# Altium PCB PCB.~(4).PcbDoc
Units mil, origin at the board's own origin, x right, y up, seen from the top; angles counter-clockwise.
Board outline 2362.2 x 1653.54 mil, 4 copper layers (Top Layer, GND, PWR, Bottom Layer), stack 61.634 mil thick; 57 components, 24 nets, 132 pads, 50 vias.
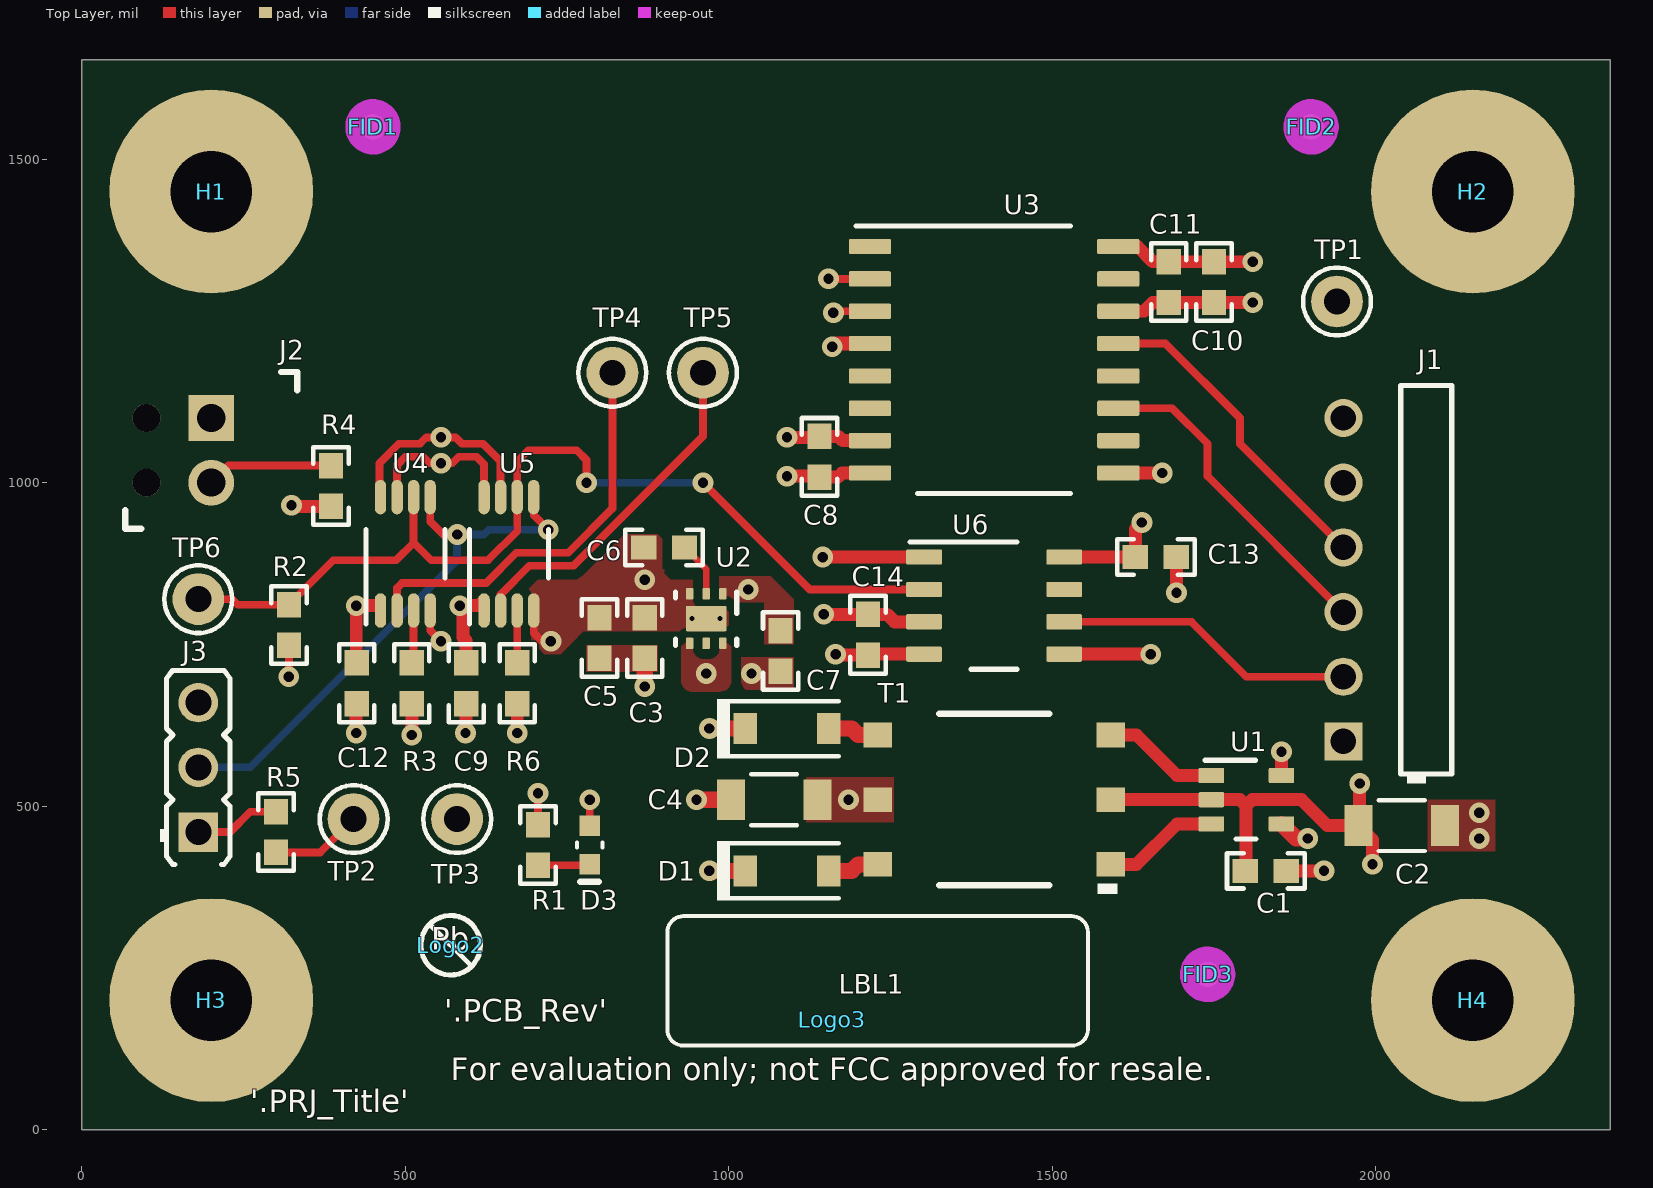
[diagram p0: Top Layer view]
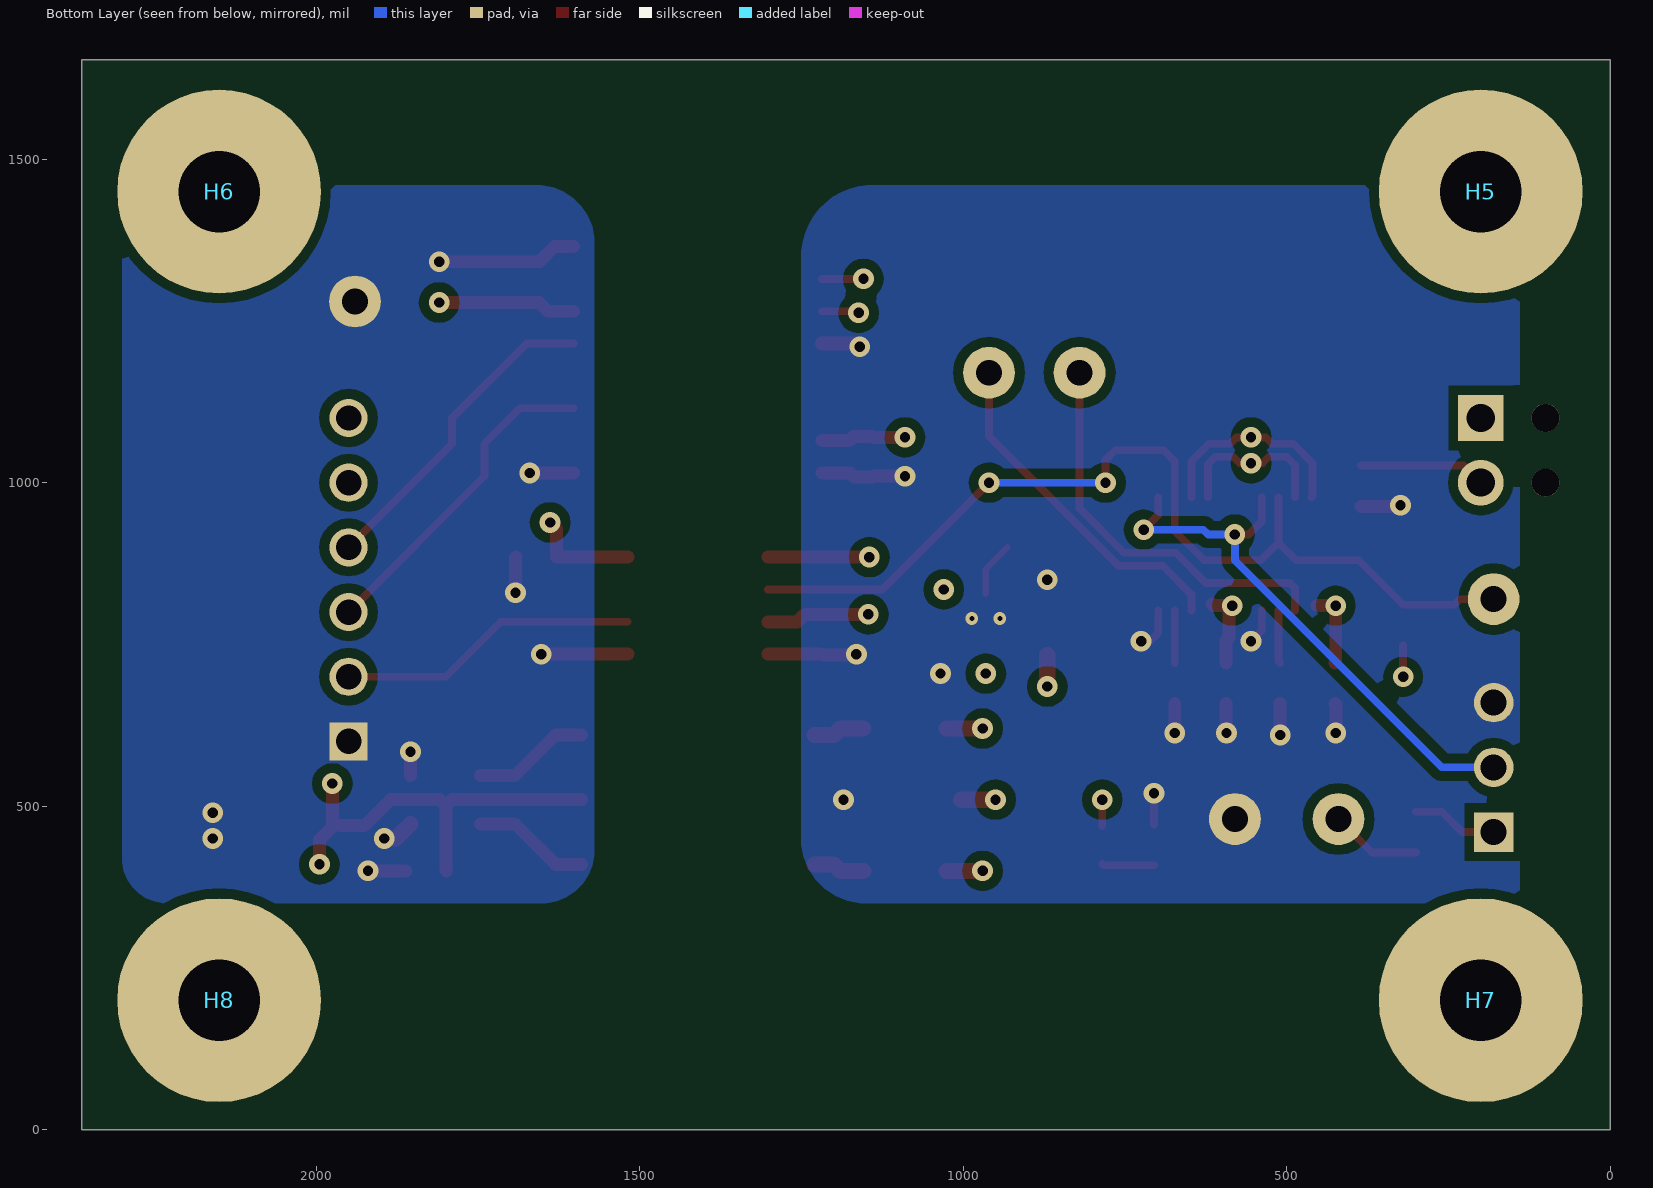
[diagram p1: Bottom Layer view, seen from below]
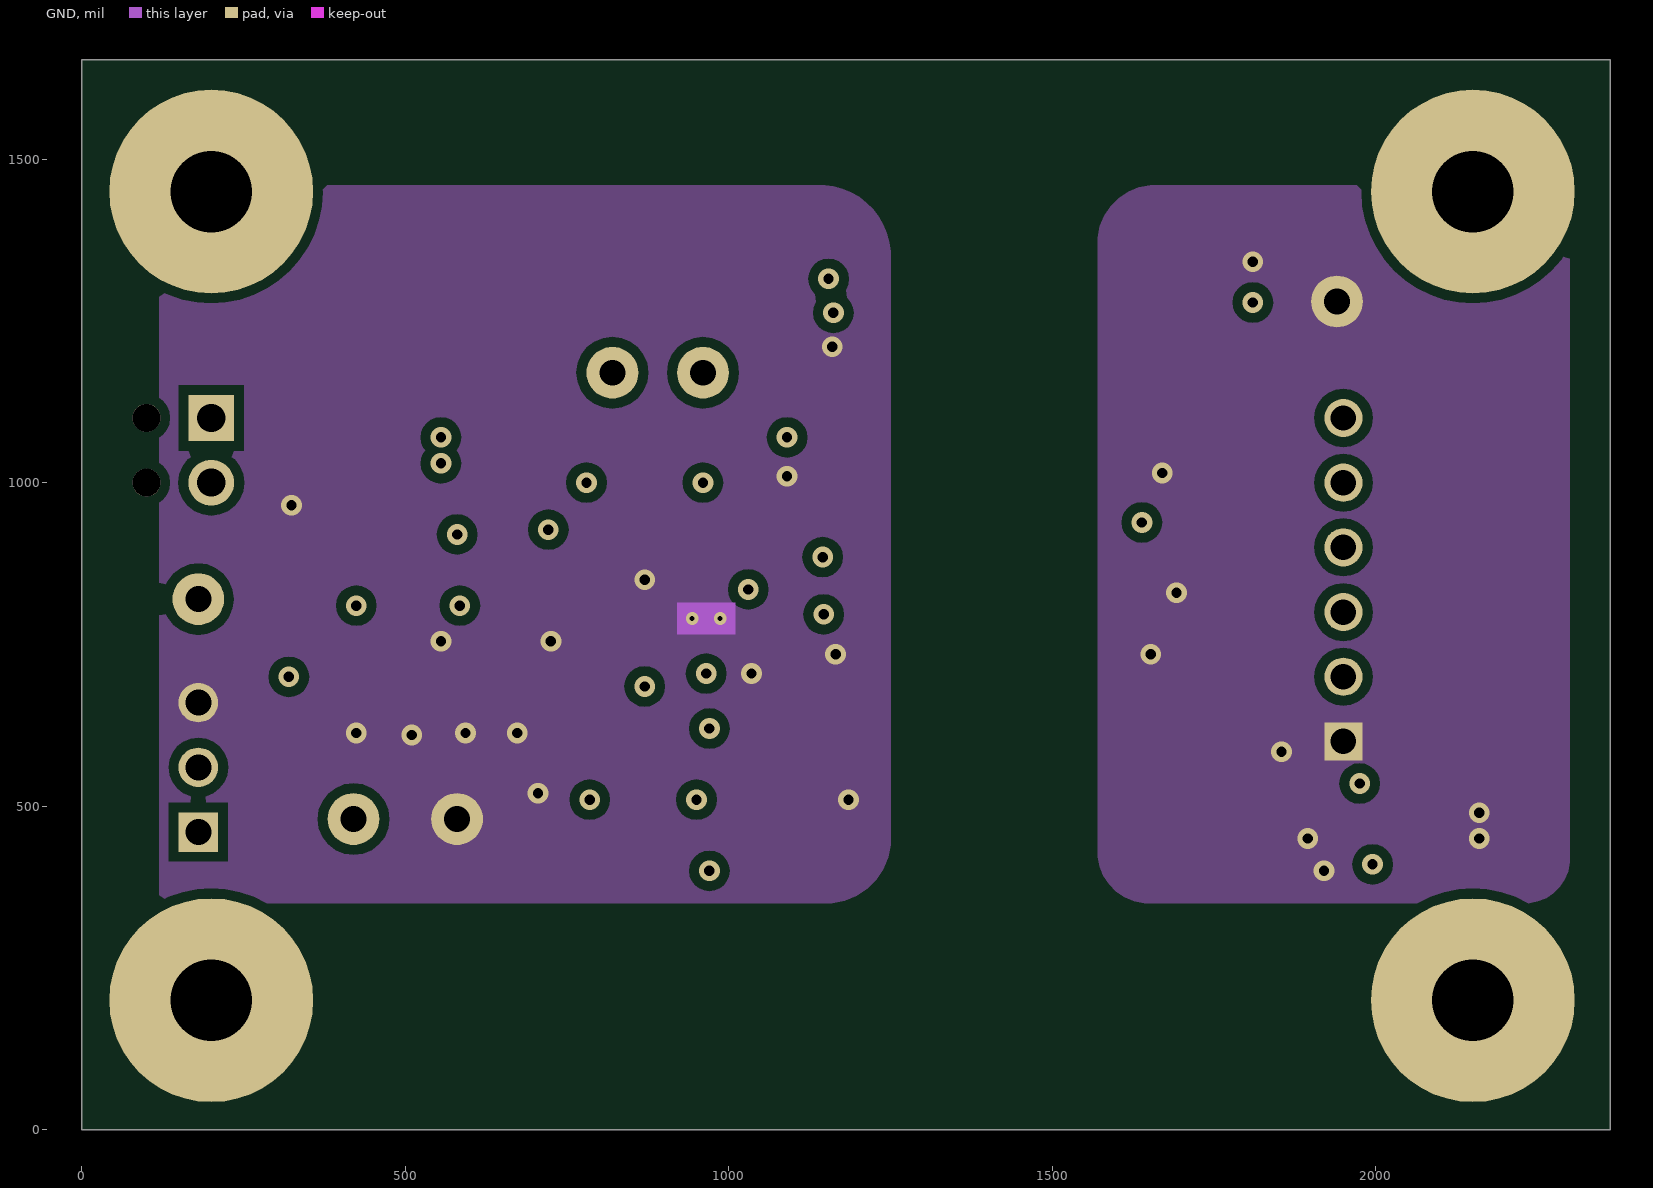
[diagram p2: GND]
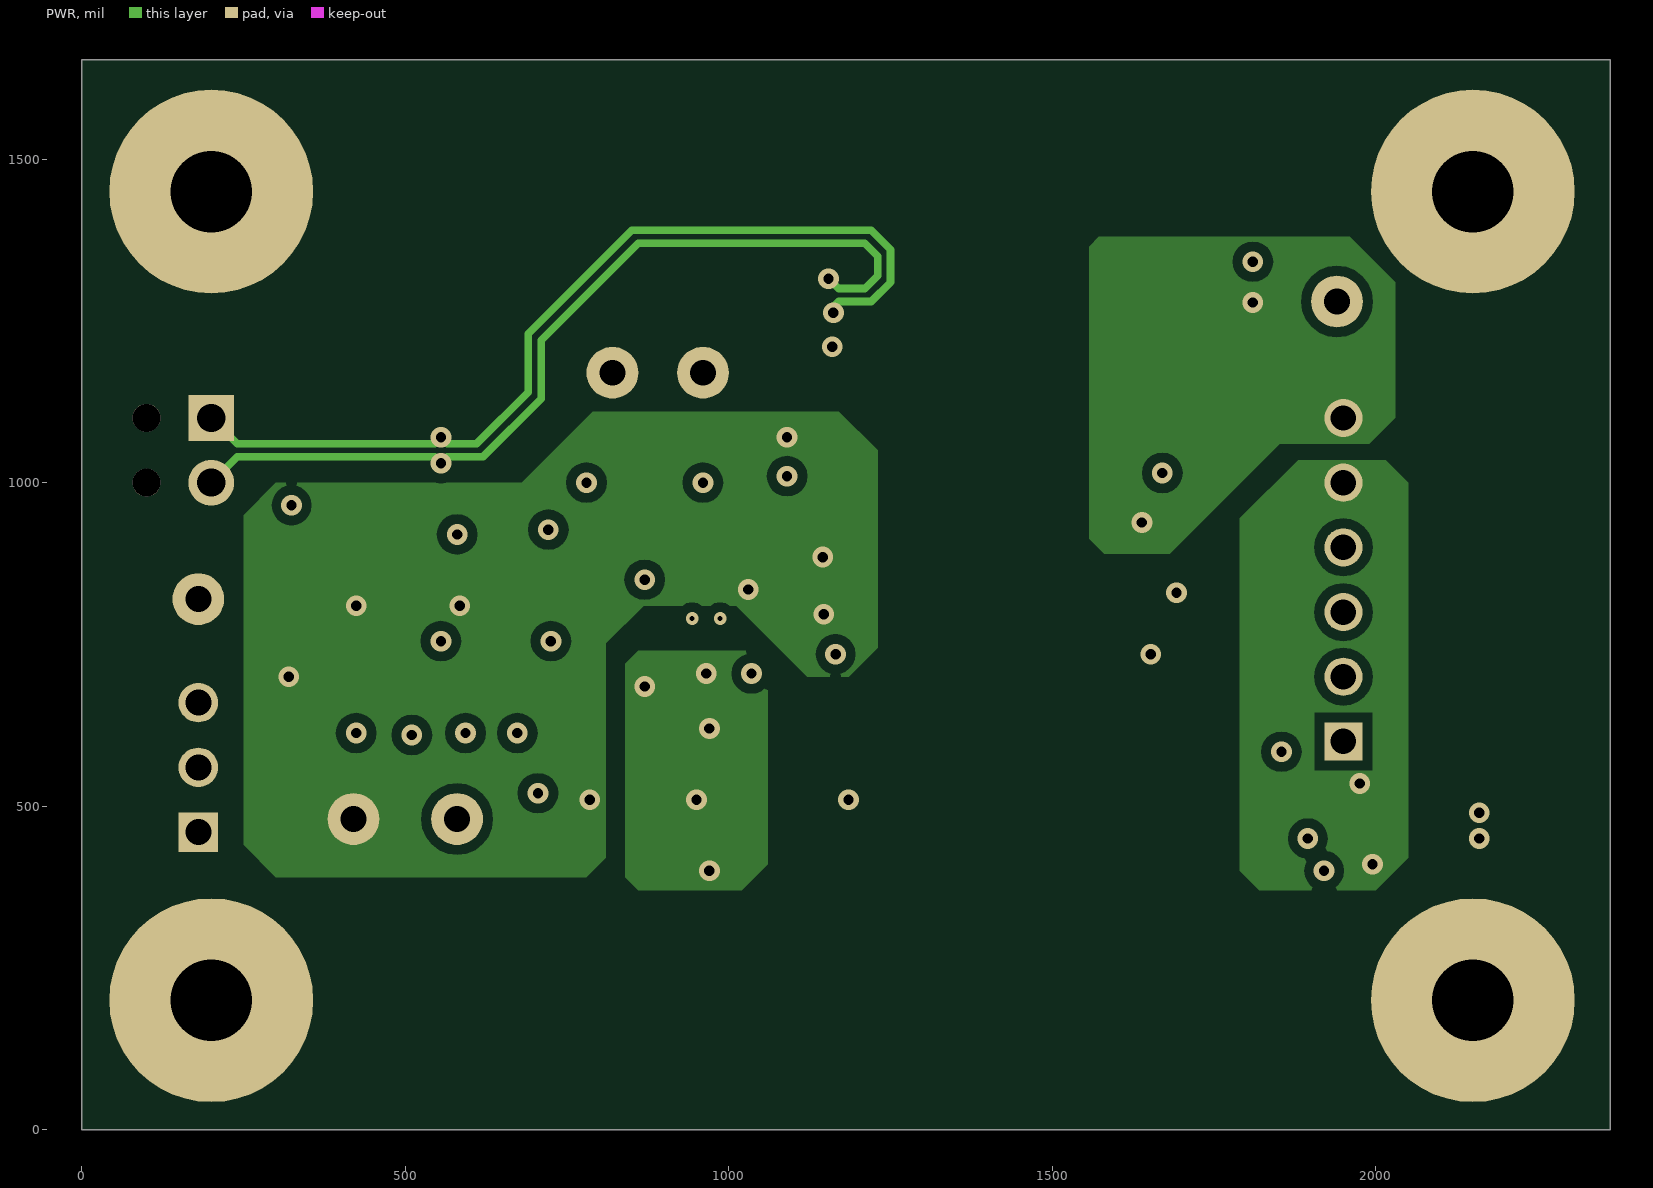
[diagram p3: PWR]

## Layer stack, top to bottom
Top Solder: solder mask 0.4, Solder Resist, Dk 3.5
Top Layer: signal copper 1.4
Dielectric1: core 18, FR-4 High Tg, Dk 4.2
GND: signal copper 1.417
Dielectric 2: prepreg 20, FR-4 High Tg, Dk 4.2
PWR: signal copper 1.417
Dielectric 3: core 18, FR-4 High Tg, Dk 4.2
Bottom Layer: signal copper 1.4
Bottom Solder: solder mask 0.4, Solder Resist, Dk 3.5

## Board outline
0,0 2362.2,0 2362.2,1653.54 0,1653.54

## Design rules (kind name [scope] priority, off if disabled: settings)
AcuteAngle [All] p1: minimum=4.50000000000000E+0001 checktracksonly=FALSE
AssemblyTestPointUsage [All] p1: valid=2
BoardOutlineClearance BoardOutlineClearance_MountingHoles [OnCopper and InComponentClass('Mounting Holes')] p1: gap=40 ignorepadtopadclearanceinfootprint=FALSE
BoardOutlineClearance BoardOutlineClearance_Poly [OnCopper and IsPoly] p2: gap=25 ignorepadtopadclearanceinfootprint=FALSE
BoardOutlineClearance [OnCopper and Not InComponentClass('Logo') and not InComponentClass('FiducialMark') and not InRegion(1000,500,4000,800) and not InPoly] p3: gap=75 ignorepadtopadclearanceinfootprint=FALSE
Clearance Clearance_Keepouts [((IsTrack Or IsArc) And Not InPoly) And IsFree and IsKeepOut vs ((IsTrack Or IsArc) And Not InPoly) And IsFree and IsKeepOut] p1: gap=0 ignorepadtopadclearanceinfootprint=FALSE
Clearance Clearance_Poly [InPolygon] p2: gap=7 ignorepadtopadclearanceinfootprint=TRUE except(15: Arc-Fill Arc-Poly Arc-Region Track-Fill Track-Poly Track-Region SMDPad-Fill SMDPad-Poly SMDPad-Region THPad-Fill THPad-Poly THPad-Region Via-Fill Via-Poly Via-Region Fill-Fill Fill-Poly Fill-Region Poly-Poly Poly-Region Region-Region)
Clearance Clearance_FiducialMark [IsKeepOut and InComponentClass('FiducialMark') vs IsPad and InComponentClass('FiducialMark')] p3: gap=0 ignorepadtopadclearanceinfootprint=FALSE
Clearance [All] p4: gap=7.85 ignorepadtopadclearanceinfootprint=TRUE
ComponentClearance ComponentClearance_MountingHoles_FiducialMarks [InComponentClass('Mounting Holes') vs InComponentClass('FiducialMark')] p1: gap=10 collisioncheckmode=3 verticalgap=10 showdistances=FALSE
ComponentClearance ComponentClearance_Shunt [InComponentClass('Header') vs InComponentClass('Shunt')] p2: gap=0 collisioncheckmode=3 verticalgap=0 showdistances=FALSE
ComponentClearance ComponentClearance_Logo [InComponentClass('Logo')] p3: gap=10 collisioncheckmode=3 verticalgap=10 showdistances=FALSE
ComponentClearance ComponentClearance_ScrewToNut [(HasFootprint('NY PMS 440 0025 PH')) vs (HasFootprint('Keystone_1902C'))] p4: gap=5 collisioncheckmode=3 verticalgap=10 showdistances=FALSE
ComponentClearance ComponentClearance_MountingHoles [InComponentClass('Mounting Holes')] p5: gap=10 collisioncheckmode=3 verticalgap=100000 showdistances=FALSE
ComponentClearance ComponentClearance_SmallPassives [HasFootprint('0201*') or HasFootprint('0402*') or HasFootprint('0508') or HasFootprint('0603*') or HasFootprint('0612') or HasFootprint('0805*') or HasFootprint('0815*') or HasFootprint('0830*') or HasFootprint('1206*') or HasFootprint('1210*') or HasFootprint('1808*') or HasFootprint('1812*') or HasFootprint('1825*') or HasFootprint('2010*') or HasFootprint('2220*') or HasFootprint('2225*') or HasFootprint('2512*') or HasFootprint('2728*') or HasFootprint('3518*') vs HasFootprint('0201*') or HasFootprint('0402*') or HasFootprint('0508') or HasFootprint('0603*') or HasFootprint('0612') or HasFootprint('0805*') or HasFootprint('0815*') or HasFootprint('0830*') or HasFootprint('1206*') or HasFootprint('1210*') or HasFootprint('1808*') or HasFootprint('1812*') or HasFootprint('1825*') or HasFootprint('2010*') or HasFootprint('2220*') or HasFootprint('2225*') or HasFootprint('2512*') or HasFootprint('2728*') or HasFootprint('3518*')] p6: gap=14.96 collisioncheckmode=3 verticalgap=10 showdistances=FALSE
ComponentClearance ComponentClearance_THtoSMT [IsThruComponent vs IsSMTComponent] p7: gap=40 collisioncheckmode=3 verticalgap=30 showdistances=FALSE
ComponentClearance ComponentClearance_THtoTH [IsThruComponent vs IsThruComponent] p8: gap=30 collisioncheckmode=3 verticalgap=30 showdistances=FALSE
ComponentClearance [All] p9: gap=20 collisioncheckmode=3 verticalgap=10 showdistances=FALSE
DiffPairsRouting [All] p1: maxlimit=100 minlimit=10 mostfreqgap=10 toplayer_minwidth=15 toplayer_maxwidth=15 toplayer_prefwidth=15 midlayer1_minwidth=15 midlayer1_maxwidth=15 midlayer1_prefwidth=15 midlayer2_minwidth=15 midlayer2_maxwidth=15 midlayer2_prefwidth=15 bottomlayer_minwidth=15 bottomlayer_maxwidth=15 bottomlayer_prefwidth=15 maxuncoupledlength=1000
FabricationTestPointUsage TestPointUsage [All] p1: valid=2 allowmultiple=FALSE
FabricationTestpoint Testpoint [All] p1: side=3 testpointundercomponent=TRUE minsize=40 maxsize=100 preferedsize=60 minholesize=0 maxholesize=40 preferedholesize=32 testpointgrid=1 allowsidetop=TRUE allowsidebottom=TRUE usegrid=TRUE gridtolerance=0.01
FanoutControl Fanout_LCC [IsLCC] p1: bgadir=Out bgaviamode=Centered fanoutstyle=Auto fanoutdirection=Alternating viagrid=1 // Fanout_LCC (Default Rule)
FanoutControl Fanout_BGA [IsBGA] p2: bgadir=Out bgaviamode=Centered fanoutstyle=Auto fanoutdirection=Alternating viagrid=1 // Fanout_BGA (Default Rule)
FanoutControl Fanout_Default [All] p4: bgadir=Out bgaviamode=Centered fanoutstyle=Auto fanoutdirection=Alternating viagrid=1 // Fanout_Default (Default Rule)
FanoutControl Fanout_Small [(CompPinCount < 5)] p5: bgadir=Out bgaviamode=Centered fanoutstyle=Auto fanoutdirection=OutThenIn viagrid=1 // Fanout_Small (Default Rule)
HoleSize [All] p1: absolutevalues=TRUE maxlimit=251 minlimit=7.87 maxpercent=80.000 minpercent=20.000
MinimumAnnularRing MinimumAnnularRing_ThermalPadVias [IsVia and InAnyComponent] p1: minimumring=5.91
MinimumAnnularRing [All] p2: minimumring=8
MinimumSolderMaskSliver MinimumSolderMaskSliver_Logo [InComponentClass('Logo') vs InComponentClass('Logo')] p1: minsoldermaskwidth=0.7
MinimumSolderMaskSliver [All] p2: minsoldermaskwidth=3.94
PlaneClearance [All] p1: clearance=5
PlaneConnect [All] p1: planeconnectstyle=Direct reliefexpansion=10 reliefentries=4 reliefconductorwidth=10 reliefairgap=10
PolygonConnect [All] p1: connectstyle=Direct reliefconductorwidth=10 reliefentries=4 polygonreliefangle="90 Angle" airgapwidth=10
RoutingVias ThermalPadVias [IsVia and InAnyComponent] p1: holewidth=7.87 width=19.68 viastyle="Through Hole" minholewidth=7.87 minwidth=19.68 maxholewidth=12.99 maxwidth=23.62
RoutingVias [All] p2: holewidth=16 width=34 viastyle="Through Hole" minholewidth=7.87 minwidth=26 maxholewidth=40 maxwidth=65
SilkToBoardRegionClearance [Not ((IsComment or IsDesignator) And (Hide <> 'False')) and not InRegion(1000,500,4000,800)] p1:
SilkToSilkClearance SilkToSilkClearance_Pb-FreeLogo [(HasFootprint('Pb-Free_Overlay_Medium') OR HasFootprint('Pb-Free_Overlay_Small')) vs (HasFootprint('Pb-Free_Overlay_Medium') OR HasFootprint('Pb-Free_Overlay_Small'))] p1: silktosilkclearance=0
SilkToSilkClearance [All] p2: silktosilkclearance=4
SilkToSolderMaskClearance SilkToComponentPadClearance [(IsPad or IsFill or IsRegion) and InAnycomponent] p1: minsilkscreentomaskgap=5 clearancetoexposedcopper=TRUE
SilkToSolderMaskClearance "Silk to Solder Mask Opening" [All] p2: minsilkscreentomaskgap=4 clearancetoexposedcopper=FALSE
SolderMaskExpansion [All] p1: expansion=1.97
Width [All] p1: maxlimit=100 minlimit=6 preferedwidth=10 checkconnectedcopper=TRUE
14 further rules are at their usual default settings.

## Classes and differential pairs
component class Label: LBL1
component class AssemblyNote: ZZ1 ZZ2 ZZ3 ZZ4
component class FiducialMark: FID1 FID2 FID3
component class EVM_Hardware: FID1 FID2 FID3 H1 H2 H3 H4 H5 H6 H7 H8 LBL1 Logo2 Logo3 ZZ1 ZZ2 ZZ3 ZZ4
component class "Mounting Holes": H1 H2 H3 H4
component class EVM_Main: C1 C2 C3 C4 C5 C6 C7 C8 C9 C10 C11 C12 C13 C14 D1 D2 D3 J1 J2 J3 R1 R2 R3 R4 R5 R6 T1 TP1 TP2 TP3 TP4 TP5 TP6 U1 U2 U3 U4 U5 U6
component class Header: J1 J3

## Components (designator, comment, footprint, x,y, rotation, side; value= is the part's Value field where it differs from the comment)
C1 "GCM188R71C104KA37J" 0603 1830,400 r180 top value=0.1uF
C2 "GRM31CR71C106KAC7L" 1206_180 2040,470 r0 top value=10uF
C3 "GCM188R71C104KA37J" 0603 870,760 r90 top value=0.1uF
C4 "GRM31CR71C106KAC7L" 1206_180 1070,510 r0 top value=10uF
C5 "GCM188R71C105KA64D" 0603 800,760 r90 top value=1uF
C6 "GRM188R71C103KA01D" 0603 900,900 r180 top value=0.01uF
C7 "GCM188R71C105KA64D" 0603 1080,740 r270 top value=1uF
C8 "GCM188R71C104KA37J" 0603 1140,1040 r270 top value=0.1uF
C9 "GCM188R71C104KA37J" 0603 594,690 r270 top value=0.1uF
C10 "GRM188R71C105KA12D" 0603 1750,1310 r270 top value=1uF
C11 "GCM188R71C104KA37J" 0603 1680,1310 r270 top value=0.1uF
C12 "GCM188R71C104KA37J" 0603 425,690 r270 top value=0.1uF
C13 "GCM188R71C104KA37J" 0603 1660,885 r0 top value=0.1uF
C14 "GCM188R71C104KA37J" 0603 1215,765 r270 top value=0.1uF
D1 "MBR0520LT1G" SOD-123 1090,400 r0 top value=20V
D2 "MBR0520LT1G" SOD-123 1090,620 r0 top value=20V
D3 "LG L29K-G2J1-24-Z" "LG L29K_GREEN" 785,440 r270 top value=Green
FID1 "Fiducial" Fiducial10-20 450,1550 r0 top
FID2 "Fiducial" Fiducial10-20 1900,1550 r0 top
FID3 "Fiducial" Fiducial10-20 1740,240 r0 top
H1 "NY PMS 440 0025 PH" "NY PMS 440 0025 PH" 200,1450 r0 top locked
H2 "NY PMS 440 0025 PH" "NY PMS 440 0025 PH" 2150,1450 r0 top locked
H3 "NY PMS 440 0025 PH" "NY PMS 440 0025 PH" 200,200 r0 top locked
H4 "NY PMS 440 0025 PH" "NY PMS 440 0025 PH" 2150,200 r0 top locked
H5 "1902C" Keystone_1902C 200,1450 r180 bottom locked
H6 "1902C" Keystone_1902C 2150,1450 r180 bottom locked
H7 "1902C" Keystone_1902C 200,200 r180 bottom locked
H8 "1902C" Keystone_1902C 2150,200 r180 bottom locked
J1 "90121-0766" Molex_90121-0766 1950,850 r90 top
J2 "1725656" CONN_1725656 200,1050 r270 top
J3 "0022284033" Molex_0022284033 180,560 r90 top
LBL1 "Size: 0.65\" x 0.20 \"" Label_650x200 1230,230 r0 top
Logo2 "Pb-Free Symbol" Pb-Free_Overlay_Small 570,285 r0 top
Logo3 "FCC disclaimer" FCC_disclaimer 1160,170 r0 top
R1 "CRCW06034K70JNEA" 0603 705,440 r270 top value=4.7k
R2 "CRCW060320K0FKEA" 0603 320,780 r270 top value=20.0k
R3 "CRCW060320K0FKEA" 0603 510,690 r90 top value=20.0k
R4 "CRCW06030000Z0EA" 0603 385,995 r90 top value=0
R5 "CRCW060320K0FKEA" 0603 300,460 r270 top value=20.0k
R6 "CRCW060320K0FKEA" 0603 673,690 r90 top value=20.0k
T1 "760390014" Wurth_760390013 1410,510 r180 top value=475uH
TP1 "5001" Keystone5001 1940,1280 r90 top
TP2 "5000" Keystone5000 420,480 r90 top
TP3 "5001" Keystone5001 580,480 r90 top
TP4 "5003" Keystone5003 820,1170 r90 top
TP5 "5003" Keystone5003 960,1170 r90 top
TP6 "5003" Keystone5003 180,820 r90 top
U1 "SN6501QDBVRQ1" DBV0005A_N 1800,510 r0 top
U2 "TPS71750QDRVRQ1" DRV0006A 965,790 r270 top
U3 "AMC1305M05QDWRQ1" DW0016B_HV 1410,1190 r0 top
U4 "INA301A2QDGKRQ1" DGK0008A_N 500,890 r90 top
U5 "INA301A2QDGKRQ1" DGK0008A_N 660,890 r90 top
U6 "ISO7710QDRQ1" D0008B_HV 1410,810 r0 top
ZZ1 "This Assembly Note is for PCB labels only" AssemblyNoteLabel 185,3938 r0 top
ZZ2 "This Assembly Note will show in the PcbDoc and associated outputs" AssemblyNote 185,3829.11 r0 top
ZZ3 "This Assembly Note will show in the PcbDoc and associated outputs" AssemblyNote 185,3740.56 r0 top
ZZ4 "This Assembly Note will show in the PcbDoc and associated outputs" AssemblyNote 185,3652 r0 top

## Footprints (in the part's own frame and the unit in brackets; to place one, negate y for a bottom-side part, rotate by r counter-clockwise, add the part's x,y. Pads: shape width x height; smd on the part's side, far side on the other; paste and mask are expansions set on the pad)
0603 [mm] "0603 from SM-752 data"
  rect 1x0.95 smd: 1(-0.8,0) 2(0.8,0)
  silkscreen extent -1.52,-0.69 1.52,0.69, body extent -0.87,-0.47 0.87,0.47, height 1
1206_180 [mm] "1206_180"
  rect 1.1x1.6 smd: 1(-1.7,0) 2(1.7,0)
  silkscreen extent -0.9,-1 0.9,1, body extent -1.75,-0.95 1.75,0.95, height 1.8
AssemblyNote [mil] "Assembly Note"
AssemblyNoteLabel [mil] "Assembly Note for PCB Labels"
CONN_1725656 [mm] "Phoenix Contact"
  rect 1.8x1.8 hole 1.1: 1(-1.27,0)
  round 1.8 hole 1.1: 2(1.27,0)
  round 1.1 hole 1.1 unplated paste+0 mask+0.152: MH1(-1.275,-2.54)
  round 1.1 hole 1.1 unplated mask+0.152: MH2(1.27,-2.54)
  silkscreen extent -3.08,-3.37 3.08,3.37, body extent -2.77,-3.1 2.77,3.1, height 8.52
D0008B_HV [mm] "SOIC, 8-Leads, Body 4.9x3.9mm, Pitch 1.27mm, HV / Isolation option"
  rrect17% 1.4x0.6 smd: 1(-2.75,1.905) 2(-2.75,0.635) 3(-2.75,-0.635) 4(-2.75,-1.905) 5(2.75,-1.905) 6(2.75,-0.635) 7(2.75,0.635) 8(2.75,1.905)
  silkscreen extent -3.3,-2.5 0.9,2.5, body extent -3,-2.45 3,2.45, height 1.63
DBV0005A_N [mm] "SOT23, 5-Leads, Body 2.9x1.6mm, Pitch 0.95mm, Lead Span 2.8mm, IPC Medium Density"
  rrect17% 1x0.6 smd: 1(-1.375,0.95) 2(-1.375,0) 3(-1.375,-0.95) 4(1.375,-0.95) 5(1.375,0.95)
  silkscreen extent -1.63,-1.55 0.38,1.55, body extent -1.42,-1.46 1.42,1.46, height 1.09
DGK0008A_N [mm] "TSOP, 8-Leads, Body 3x3mm, Pitch 0.65mm, IPC Medium Density"
  oval 1.35x0.45 smd: 1(-2.225,0.975) 2(-2.225,0.325) 3(-2.225,-0.325) 4(-2.225,-0.975) 5(2.225,-0.975) 6(2.225,-0.325) 7(2.225,0.325) 8(2.225,0.975)
  silkscreen extent -2.75,-1.55 0.95,1.55, body extent -2.45,-1.5 2.45,1.5, height 0.96
DRV0006A [mm] "SON, 6-Leads, Body 2x2mm, Pitch 0.65mm, Thermal Pad 1.6x1mm, TI Recommended"
  rrect33% 0.45x0.3 smd: 1(-0.975,0.65) 2(-0.975,0) 3(-0.975,-0.65) 4(0.975,-0.65) 5(0.975,0) 6(0.975,0.65)
  rrect14% 1x0.7 on Top Paste: 7(0,0.45) 7(0,-0.45)
  rrect10% 1x1.6 smd paste-0.5: 7(0,0)
  silkscreen extent -1.05,-1.2 1.05,1.2, body extent -1.05,-1.05 1.05,1.05, height 0.81
DW0016B_HV [mm] "High voltage version of DW0016B"
  rrect17% 1.65x0.6 smd: 1(-4.875,4.445) 2(-4.875,3.175) 3(-4.875,1.905) 4(-4.875,0.635) 5(-4.875,-0.635) 6(-4.875,-1.905) 7(-4.875,-3.175) 8(-4.875,-4.445) 9(4.875,-4.445) 10(4.875,-3.175) 11(4.875,-1.905) 12(4.875,-0.635) 13(4.875,0.635) 14(4.875,1.905) 15(4.875,3.175) 16(4.875,4.445)
  silkscreen extent -5.43,-5.25 3,5.25, body extent -5.14,-5.13 5.14,5.13, height 2.5
FCC_disclaimer [mil]
Fiducial10-20 [mm]
  round 1 smd mask+0.5: 1(0,0)
  Top Layer keep-out circle w1.178: c0,0 r0.5
Keystone5000 [mil] "For Keystone 500x miniature loop terminals"
  round 80 hole 40: 1(0,0)
  silkscreen extent -52,-52 52,52, body extent -49,-49 49,49, height 182
Keystone5001 [mil] "For Keystone 500x miniature loop terminals"
  round 80 hole 40: 1(0,0)
  silkscreen extent -52,-52 52,52, body extent -49,-49 49,49, height 182
Keystone5003 [mil] "For Keystone 500x miniature loop terminals"
  round 80 hole 40: 1(0,0)
  silkscreen extent -52,-52 52,52, body extent -49,-49 49,49, height 182
Keystone_1902C [mil] "Hex Standoff, 4-40 threaded, nylon"
  body extent -145,-126 146,126, height 501
Label_650x200 [mil] "Thermal Transfer Label"
  silkscreen extent -325,-100 325,100, body extent -325,-100 325,100, height 1
"LG L29K_GREEN" [mm] "OSRAM"
  rect 0.8x0.8 smd paste-0.4: 1(-0.75,0) 2(0.75,0)
  silkscreen extent -0.1,-0.5 1.45,0.5, body extent -0.9,-0.45 0.9,0.45, height 0.67
Molex_90121-0766 [mm] "Header, 2.54mm, 6x1, R/A, TH"
  rect 1.5x1.5 hole 1: 1(-6.35,0)
  round 1.5 hole 1: 2(-3.81,0) 3(-1.27,0) 4(1.27,0) 5(3.81,0) 6(6.35,0)
  silkscreen extent -8,-4.25 7.62,-2.25, body extent -7.62,-11 7.62,0.32, height 3.63
Molex_0022284033 [mm] "Header, 2.54mm, 3x1, TH"
  rect 1.55x1.55 hole 1.02: 1(-2.54,0)
  round 1.55 hole 1.02: 2(0,0) 3(2.54,0)
  silkscreen extent -3.81,-1.24 3.81,1.5, body extent -3.81,-1.24 3.81,1.24, height 8.4
"NY PMS 440 0025 PH" [mm] "4-40 nylon screw and mounting hole"
  round 8 hole 3.2: 1(0,0)
  body extent -3.3,-3.3 3.3,3.3, height 2.69
Pb-Free_Overlay_Small [mil]
  silkscreen extent -46,-46 46,46
SOD-123 [mm] "On Semi recommended land pattern"
  rect 0.915x1.22 smd: 1(-1.637,0) 2(1.637,0)
  silkscreen extent -2.74,-1.17 2.03,1.17, body extent -1.93,-0.9 1.93,0.9, height 1.35
Wurth_760390013 [mil] "Wurth"
  rect 44x38 smd: 1(-180,100) 2(-180,0) 3(-180,-100) 4(180,-100) 5(180,0) 6(180,100)
  silkscreen extent -190,-132 85,145, body extent -198,-135 198,130, height 166

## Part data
C1 C3 C8 C9 C11 C12 C13 C14: "CAP, CERM, 0.1 µF, 16 V,+/- 10%, X7R, AEC-Q200 Grade 1, 0603", Cap_Case=0603, Manufacturer=MuRata, Supplier Part Number 1=490-8015-1-ND, TempCo=X7R, Tolerance_%=10, Value1=Unknown, Value2=16V, ValueDisplayed=0.1µF
C2 C4: "CAP, CERM, 10 µF, 16 V,+/- 10%, X7R, 1206", Cap_Case=1206, Manufacturer=MuRata, Supplier Part Number 1=490-3911-1-ND, TempCo=X7R, Tolerance_%=10, Value1=Unknown, Value2=16V, ValueDisplayed=10µF
C5 C7: "CAP, CERM, 1 µF, 16 V,+/- 10%, X7R, AEC-Q200 Grade 1, 0603", Cap_Case=0603, Manufacturer=MuRata, Supplier Part Number 1=490-5241-6-ND, TempCo=X7R, Tolerance_%=10, Value1=Unknown, Value2=16V, ValueDisplayed=1µF
C6: "CAP, CERM, 0.01 µF, 16 V,+/- 10%, X7R, 0603", Cap_Case=0603, Manufacturer=MuRata, Supplier Part Number 1=490-1525-1-ND, TempCo=X7R, Tolerance_%=10, Value1=Unknown, Value2=16V, ValueDisplayed=0.01µF
C10: "CAP, CERM, 1 µF, 16 V,+/- 10%, X7R, 0603", Cap_Case=0603, Manufacturer=MuRata, Supplier Part Number 1=490-3900-1-ND, TempCo=X7R, Tolerance_%=10, Value1="0.011 ohm", Value2=16V, ValueDisplayed=1µF
D1 D2: "Diode, Schottky, 20 V, 0.5 A, SOD-123", Manufacturer="ON Semiconductor", Supplier Part Number 1=MBR0520LT1GOSCT-ND, Value1=0.5A, Value2=0.385V
D3: "LED, Green, SMD", Color=green, Manufacturer=OSRAM, Supplier Part Number 1=475-2709-1-ND, Value1=W, Value2=1.7V
FID1 FID2 FID3: "Fiducial mark.  There is nothing to buy or mount.", Manufacturer=N/A
H1 H2 H3 H4: "Machine Screw, Round, #4-40 x 1/4, Nylon, Philips panhead", DigiKeyPartNumber=H542-ND, Manufacturer="B&F Fastener Supply"
H5 H6 H7 H8: "Standoff, Hex, 0.5\"L #4-40 Nylon", Manufacturer=Keystone, Supplier Part Number 1=36-1902C-ND
J1: "Header, 2.54mm, 6x1, Gold, R/A, TH", Color=Black, Current_A=3, Manufacturer=Molex, Supplier Part Number 1=WM8112-ND, Voltage_V=350
J2: "Terminal Block, 100mil, 2x1, 6A, 63V, TH", Manufacturer="Phoenix Contact", Supplier Part Number 1=71C4107
J3: "Header, 2.54mm, 3x1, Tin, TH", Color=Black, Current_A=4, Manufacturer=Molex, Supplier Part Number 1=WM50016-03-ND, Voltage_V=250
LBL1: library part THT-14-423-10, "Thermal Transfer Printable Labels, 0.650\" W x 0.200\" H - 10,000 per roll", Manufacturer=Brady, Supplier Part Number 1=97C5133
Logo2: library part Pb-Free
Logo3: library part FCC_disclaimer, "FCC_disclaimer"
R1: "RES, 4.7 k, 5%, 0.1 W, 0603", Manufacturer=Vishay-Dale, Power_W=0.1, Supplier Part Number 1=541-4.7KGCT-ND, TempCo="200 ppm/C", Tolerance_%=5, Value1=5%, Value2=0.1W, Value_Code=4k70, ValueDisplayed=4.7k
R2 R3 R5 R6: "RES, 20.0 k, 1%, 0.1 W, 0603", Manufacturer=Vishay-Dale, Power_W=0.1, Supplier Part Number 1=541-20.0KHCT-ND, TempCo="100 ppm/C", Tolerance_%=1, Value1=1%, Value2=0.1W, Value_Code=20k0, ValueDisplayed=20.0k
R4: "RES, 0, 5%, 0.1 W, 0603", Manufacturer=Vishay-Dale, Power_W=0.1, Supplier Part Number 1=541-0.0GCT-ND, TempCo="200 ppm/C", Tolerance_%=5, Value1=5%, Value2=0.1W, Value_Code=0000, ValueDisplayed=0
T1: "Transformer, 475uH, SMT", Manufacturer="Wurth Elektronik", Supplier Part Number 1=732-4458-1-ND, ValueDisplayed=475µH
TP1 TP3: "Test Point, Miniature, Black, TH", Color=Black, Manufacturer=Keystone, Supplier Part Number 1=36-5001-ND
TP2: "Test Point, Miniature, Red, TH", Color=Red, Manufacturer=Keystone, Supplier Part Number 1=36-5000-ND
TP4 TP5 TP6: "Test Point, Miniature, Orange, TH", Color=Orange, Manufacturer=Keystone, Supplier Part Number 1=36-5003-ND
U1: "Automotive Low-Noise 350 mA, 410 kHz Transformer Driver, DBV0005A (SOT-23-5)", Alternate Manufacturer="Texas Instruments"
U2: library part CMP-0082419-1, "Low Noise, High-Bandwidth PSRR Low-Dropout 150mA Linear Regulator for Automotive Applications, DRV0006A (WSON-6)", Alternate Manufacturer="Texas Instruments", Operating Temperature Range="-40 to 125 C", Rating=Automotive
U3: library part CMP-0082424-1, "Automotive Reinforced Isolated Modulator With +/-50mV Input and CMOS Interface, DW0016B (SOIC-16)", Alternate Manufacturer="Texas Instruments", Alternate PartNumber=AMC1305M05QDWQ1, Operating Temperature Range="-40 to 125 C", Rating=Automotive
U4 U5: library part CMP-0082409-1, "AEC-Q100, 36V, Low-/High-side, Voltage Output CSA with Comparator, DGK0008A (VSSOP-8)", Alternate Manufacturer="Texas Instruments", Alternate PartNumber=INA301A2QDGKTQ1, Operating Temperature Range="-40 to 125 C", Rating=Automotive
U6: library part CMP-0082405-1, "Automotive, High Speed, Robust EMC Reinforced Single-Channel Digital Isolator, D0008B (SOIC-8)", Alternate Manufacturer="Texas Instruments", Alternate PartNumber=ISO7710QDQ1, Operating Temperature Range="-40 to 125 C", Rating=Automotive
ZZ1: library part AssemblyNoteLabel
ZZ2 ZZ3 ZZ4: library part AssemblyNote

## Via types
v1: diameter 32, hole 16, Top Layer to Bottom Layer, 48 vias
v2: diameter 19.68, hole 7.87, Top Layer to Bottom Layer, 2 vias

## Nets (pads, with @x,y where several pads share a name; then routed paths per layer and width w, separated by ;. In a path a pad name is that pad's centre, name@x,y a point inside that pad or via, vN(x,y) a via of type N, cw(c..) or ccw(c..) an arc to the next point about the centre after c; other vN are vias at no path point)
5V_ISO: C7.1 C8.1 C9.1 C12.1 C14.1 D3.1 R2.2 R5.2 TP2.1 U2.1 U3.7 U4.1 U5.1 U6.1 U6.3 | length 921
  Top Layer w12: R5.2 368.5,428.5 TP2.1 ; v1(320,700) R2.2 ; D3.1 v1(785,510)
  Top Layer w20: C12.1 424.13,722.36 v1(424.13,810) U4.1@452.76,810 ; C9.1 594,756 588.87,761.13 588.87,805.26 v1(584.13,810) 612.76,810 U5.1@615.47,812.72 ; v1(1090,1070) 1138.5,1070 C8.1 1169.77,1071.5 1176.27,1065 U3.7 ; v1(1145,885) U6.1 ; v1(1146.5,796.5) C14.1 1244.77,796.5 1256.27,785 U6.3
  other v1: 1030,835
ALERT: R2.1 TP6.1 U4.6 U5.6 U6.2 | length 1489.6
  Top Layer w12: TP6.1 232.5,820 241,811.5 R2.1 388.5,880 485.59,880 512.8,907.2 ; U4.6 512.8,907.2 ; v1(780,1000) 780,1035 765,1050 690,1050 672.8,1032.8 U5.6 672.8,925.19 627.61,880 540,880 512.8,907.2 ; v1(960,1000) 1125,835 U6.2
  Bottom Layer w12: v1(780,1000) v1(960,1000)
CLKIN: J1.4 U3.13 | length 502
  Top Layer w12: U3.13 1675,1215 1790,1100 1790,1060 J1.4
DOUT: J1.3 U3.11 | length 507.8
  Top Layer w12: U3.11 1685,1115 1740,1060 1740,1010 J1.3
GND: C1.1 C2.2 C10.1 C11.1 C13.2 J1.1 TP1.1 U1.4 U1.5 U3.9 U3.16 U6.5 | length 622.4
  Top Layer w20: U6.5 v1(1652,735) ; U3.9 v1(1670,1015) ; U3.16 1631.73,1365 1655.24,1341.5 v1(1810,1341.5) ; v1@1690,830 v1@1691.5,831.5 ; C13.2 1692,884.5 v1(1692,830) ; U1.5 v1(1854.13,584.13) ; C1.1 v1(1920,400)
  Top Layer w25: U1.4 1876.73,450 v1(1895,450)
  other v1: 2160,450 2160,490
ISOGND: C3.2 C4.2 C5.2 C6.2 C7.2 C8.2 C9.2 C12.2 C14.2 J3.3 R1.1 R3.1 R4.1 R6.1 T1.5 TP3.1 U2.3 U2.7@965,790 U3.4 U3.8 U4.4 U5.4 U6.4 | length 733.6
  Top Layer w12: U4.4 538.39,771.61 v1(555,755) ; U5.4 698.39,767.6 710.98,755 v1(725,755) ; R1.1 v1(705,520)
  Top Layer w20: v1@323.5,963.5 R4.1 ; v1(424,613) 424,657.5 C12.2 ; v1(510,610) R3.1 ; v1(593,613) 594,614 C9.2 ; v1(673,613) R6.1 ; v1(1090,1010) 1138.5,1010 C8.2 1168.5,1008.5 1175,1015 U3.8 ; v1(1165,735) 1166.5,733.5 C14.2 ; C14.2@1220,735 U6.4
  Top Layer w21.81: v1@1165,1215 U3.4
  other v1: 1185,510 1035,705 870,850 324.13,965 1160,1210
  other v2: 943.35,790 986.65,790
NetC3_1: C3.1 C4.1 C5.1 D1.1 D2.1 U2.4 U2.6 | length 212.6
  Top Layer w25: v1(870,685) C3.1@870,733.5 ; v1(950,510) C4.1 ; v1(970,400) D1.1 ; v1(970,620) D2.1
  other v1: 965,705
NetC6_1: C6.1 U2.2 | length 85.5
  Top Layer w10: C6.1 965,866.5 U2.2
NetD1_2: D1.2 T1.6 | length 79.7
  Top Layer w25: D1.2 1190,400 1200,410 T1.6
NetD2_2: D2.2 T1.4 | length 79.7
  Top Layer w25: D2.2 1190,620 1200,610 T1.4
NetD3_2: D3.2 R1.2 | length 80.8
  Top Layer w12: R1.2 783.03,408.5 D3.2
NetJ3_1: J3.1 R5.1 | length 133
  Top Layer w12: J3.1 229,460 260.5,491.5 R5.1
NetR3_2: R3.2 U4.3 | length 82.1
  Top Layer w12: R3.2 512.8,724.29 U4.3
NetR6_2: R6.2 U5.3 | length 81
  Top Layer w12: U5.3 673,802.2 R6.2
NetT1_1: T1.1 U1.3 | length 181.8
  Top Layer w20: T1.1 1630,410 1692.6,472.6 U1.3
NetT1_3: T1.3 U1.1 | length 181.8
  Top Layer w20: T1.3 1630,610 1692.6,547.4 U1.1
NetTP4_1: TP4.1 U4.2 | length 628.5
  Top Layer w12: U4.2 487.2,837.2 495,845 625,845 671.59,891.59 751.59,891.59 820,960 TP4.1
NetTP5_1: TP5.1 U5.2 | length 537.1
  Top Layer w12: U5.2 647.2,827.2 691.71,871.71 759.82,871.71 960,1071.89 TP5.1
OC_OUT: J1.2 U6.6 | length 466.9
  Top Layer w12: U6.6 1715,785 1800,700 J1.2
OC_RST: J3.2 U4.5 U5.5 | length 863.6
  Top Layer w12: U4.5 538.65,977.34 538.65,940 558.65,920 v1(580,920) ; U5.5 698.39,950.04 v1(721.02,927.4)
  Bottom Layer w12: J3.2 260,560 580,880 v1(580,920) 621.35,920 628.76,927.4 v1(721.02,927.4)
SHUNT_HS: J2.1 U3.3 U4.8 U5.7 | length 1850.9
  Top Layer w12: U4.8 460,979.21 460,1030 490,1060 522.5,1060 532.5,1070 v1(555,1070) 577.5,1070 587.5,1060 620,1060 647.2,1032.8 U5.7 ; v1@1155,1265 U3.3
  PWR w12: J2.1@220,1100 J2.1 240,1060 545,1060 v1(555,1070) 565,1060 610,1060 690,1140 690,1230 850,1390 1220,1390 1250,1360 1250,1310 1220,1280 1170,1280 v1@1155,1265
  other v1: 1161.63,1262.5
SHUNT_LS: J2.2 R4.2 U3.2 U4.7 U5.8 | length 1884.3
  Top Layer w12: J2.2 226.5,1026.5 R4.2 ; U4.7 487.2,1027.2 500,1040 527.5,1040 537.5,1030 v1(555,1030) 572.5,1030 582.5,1040 610,1040 621.61,1028.39 U5.8 ; v1@1155,1315 U3.2
  PWR w12: J2.2 240,1040 545,1040 v1(555,1030) 565,1040 620,1040 710,1130 710,1220 860,1370 1210,1370 1230,1350 1230,1320 1210,1300 1170,1300 v1@1155,1315
  other v1: 1154.13,1315
VCC_5V: C1.2 C2.1 J1.5 T1.2 U1.2 | length 623.3
  Top Layer w20: T1.2 U1.2 1790,510 1799.51,500.49 ; C1.2 1799.51,401 1799.51,500.49 ; C2.1@1963.07,470 1925,470 1885,510 1809.02,510 1799.51,500.49 ; v1@1975,525 1975,471.93 C2.1 1995,448.07 v1(1995,410)
  other v1: 1975,535
VCC_IO: C10.2 C11.2 C13.1 J1.6 U3.14 U6.8 | length 381.5
  Top Layer w20: U6.8 C13.1 1628.5,928.5 v1(1638.5,938.5) ; U3.14 1641.73,1265 1655.24,1278.5 C11.2 v1(1810,1278.5)
pads on no net: FID1.1 FID2.1 FID3.1 H1.1 H2.1 H3.1 H4.1 J2.MH1 J2.MH2 U2.5 U2.7@947.28,790 U2.7@982.72,790 U3.1 U3.5 U3.6 U3.10 U3.12 U3.15 U6.7

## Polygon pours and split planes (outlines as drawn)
ISOGND on Top Layer "TOP_LAYER_ISOGND_P010" (solid, remove dead copper, pour order 10): 1120,545 1255,545 1255,475 1120,475
GND on Top Layer "TOP_LAYER_GND_P008" (solid, remove dead copper, pour order 8): 2185,510 2080,510 2080,430 2185,430
NetC3_1 on Top Layer "TOP_LAYER_NETC3_1_P046" (solid, remove dead copper, pour order 46): 926.62,761 1003.62,761 1003.62,693.62 cw(c986.55,693.62) 986.55,676.55 943.45,676.55 cw(c943.45,693.38) 926.62,693.38
5V_ISO on Top Layer "TOP_LAYER_5V_ISO_P050" (solid, remove dead copper, pour order 50): 985,815 985,855 1060,855 1060,815
5V_ISO on Top Layer "TOP_LAYER_5V_ISO_P054" (solid, remove dead copper, pour order 54): 1100,750 1100,820 1065,855 1055,855 1055,750
ISOGND on Top Layer "TOP_LAYER_ISOGND_P056" (solid, remove dead copper, pour order 56): 1100,680.02 1100,730 1015,730 1015,680.02
NetC3_1 on Top Layer "TOP_LAYER_NETC3_1_P060" (solid, remove dead copper, pour order 60): 890,708 780,708 780,749 890,749
ISOGND on Top Layer "VS" (solid, pour order 74): 890,920 900,910 900,860 910,850 945,850 950,845 950,820 960,810 995,810 1000,805 1000,775 995,770 775,770 740,735 715,735 690,760 690,835 705,850 765,850 835,920
GND on GND "GND_GND_P002" (solid, remove dead copper, pour order 2): 2300,1460 2300,420 cw(c2230,420) 2230,350 1650,350 cw(c1650,430) 1570,430 1570,1370 cw(c1660,1370) 1660,1460
ISOGND on GND "GND_ISOGND_P020" (solid, pour order 20): 1250,450 1250,1350 ccw(c1140,1350) 1140,1460 120,1460 120,350 1150,350 ccw(c1150,450)
VCC_5V on PWR "VS" (solid, pour order 72): 2015,1035 2050,1000 2050,420 2000,370 1820,370 1790,400 1790,945 1880,1035
VCC_IO on PWR "VS" (solid, pour order 70): 1960,1380 2030,1310 2030,1100 1990,1060 1851.65,1060 1681.65,890 1580,890 1556.74,913.26 1556.74,1364.65 1572.09,1380
NetC3_1 on PWR "VS" (solid, pour order 68): 860,740 1031.46,740 1060,711.46 1060,410 1020,370 860,370 840,390 840,720
5V_ISO on PWR "VS" (solid, pour order 66): 680,1000 790,1110 1170,1110 1230,1050 1230,745.02 1184.98,700 1121.46,700 1011.46,810 868.54,810 810,751.46 810,420 780,390 300,390 250,440 250,950 300,1000
GND on Bottom Layer "BOTTOM_LAYER_GND_P040" (solid, remove dead copper, pour order 40): 1570,431.94 1570,1370 cw(c1660,1370) 1660,1460 2300,1460 2300,420 cw(c2230,420) 2230,350 1651.94,350 cw(c1651.94,431.94)
ISOGND on Bottom Layer "BOTTOM_LAYER_ISOGND_P038" (solid, remove dead copper, pour order 38): 1250,450 1250,1350 ccw(c1140,1350) 1140,1460 140,1460 140,350 1150,350 ccw(c1150,450)

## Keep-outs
Keep-Out Layer:
  text ".Layer_Name" at 577,-858.49 h60

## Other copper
Top Layer:
  text ".Layer_Name" at 577,-858.49 h60
GND:
  rectangle net ISOGND: 920,765 1010,815
  text "'.Layer_Name'" at 595,-865 h60
PWR:
  text "'.Layer_Name'" at 585,-860 h60
Bottom Layer:
  text ".Layer_Name" at 577,-858.49 h60

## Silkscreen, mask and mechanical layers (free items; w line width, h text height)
Top Overlay:
  text "'.PCB_Rev'" at 560,155 h60
  text "'.PRJ_Title'" at 260,15 h60
  text ".Layer_Name" at 577,-858.49 h60
Bottom Overlay:
  text ".Layer_Name" at 577,-858.49 h60
Top Paste:
  text ".Layer_Name" at 577,-858.49 h60
Bottom Paste:
  text ".Layer_Name" at 577,-858.49 h60
Top Solder:
  text ".Layer_Name" at 577,-858.49 h60
  text ".Layer_Name" at 577,-858.49 h60
Bottom Solder:
  text ".Layer_Name" at 577,-858.49 h60
M1 Board Outline:
  the board outline again, w10
  text "'.Layer_Name'" at 580,-855 h72.83
M2 Board Dimensions:
  rectangle: 125,-400 500,-275
  rectangle: 0,-275 125,-150
  lines w7: 0,-275 1000,-275 ; 125,-400 125,-150 ; 250,-400 250,-150 ; 500,-400 500,-150 ; 750,-400 750,-150 ; 0,-400 0,-150 1000,-150 1000,-400 0,-400
M5 Assembly Top:
  lines w10: -292,-930.17 6308,-930.17 ; -292,-726.83 6310,-726.83 ; -292,-523.5 -292,-1133.5 3713,-1133.5 6310,-1133.5 6310,-523.5 -291.5,-523.5 -291.5,-1133.5 1284,-1133.5 ; 2173,-1133.5 2173,-523.5 ; 3440,-726.83 3440,-523.5 ; 4280,-726.83 4280,-523.5 ; 4902,-1140 4902,-937.17
  text "COMPONENTS MARKED 'DNP' SHOULD NOT BE POPULATED." at 1153.5,-318.5 h60
  text "ASSEMBLY VARIANT:" at 1153,-434 h60
  text ".VariantName" at 2189,-434 h60
  text "PCB VIEWED FROM TOP SIDE" at -228.5,-655.67 h60
  text "BOARD #:" at 2248,-655.67 h60
  text ".PRJ_Number" at 2793.5,-655.67 h60
  text "REV:" at 3638,-655.67 h60
  text ".PCB_Rev" at 3929.5,-655.67 h60
  text "SVN REV:" at 4476,-655.67 h60
  text ".VersionControl_RevNumber" at 4982,-655.67 h60
  text "TID #:" at 2248,-859 h60
  text ".TID" at 2793.5,-859 h60
  text "'.Layer_Name'" at 585,-860 h60
  text ".plot_File_Name" at 430,-1060 h40
  text "PLOT NAME =" at -228.5,-1064.34 h60
  text "GENERATED    :" at 2250,-1064.34 h60
  text ".Print_Date" at 3119.5,-1064.34 h60
  text ".Print_Time" at 3848.5,-1064.34 h60
  text "TEXAS INSTRUMENTS" at 5113,-1064.34 h60
M6 Assembly Bottom:
  lines w10: -292.5,-727.33 6309.5,-727.33 ; -290.5,-930.67 6309.5,-930.67 ; 1115.5,-1140.5 1115.5,-937.67 ; 1737.5,-727.33 1737.5,-524 ; 2577.5,-727.33 2577.5,-524 ; 3844.5,-1134 3844.5,-524 ; 4733.5,-1134 6309,-1134 6309,-524 -292.5,-524 -292.5,-1134 2304.5,-1134 6309.5,-1134 6309.5,-524
  text "COMPONENTS MARKED 'DNP' SHOULD NOT BE POPULATED." at 6102,-318 h60
  text ".VariantName" at 5058,-434 h60
  text "ASSEMBLY VARIANT:" at 6097,-434 h60
  text ".VersionControl_RevNumber" at 1035.5,-656.17 h60
  text "SVN REV:" at 1541.5,-656.17 h60
  text ".PCB_Rev" at 2088,-656.17 h60
  text "REV:" at 2379.5,-656.17 h60
  text ".PRJ_Number" at 3224,-656.17 h60
  text "BOARD #:" at 3769.5,-656.17 h60
  text "PCB VIEWED FROM BOTTOM SIDE" at 6246,-656.17 h60
  text "'.Layer_Name'" at 5940,-835 h60
  text ".TID" at 3224,-859.5 h60
  text "TID #:" at 3769.5,-859.5 h60
  text "TEXAS INSTRUMENTS" at 904.5,-1064.84 h60
  text ".Print_Time" at 2169,-1064.84 h60
  text ".Print_Date" at 2898,-1064.84 h60
  text "GENERATED    :" at 3767.5,-1064.84 h60
  text ".plot_File_Name" at 5590,-1065 h40
  text "PLOT NAME =" at 6246,-1064.84 h60
M9 Title Sheet:
  drawing of 57 lines, arcs and shapes, not listed
  text "1" at 739.84,8036.5 h70
  text "2" at 3235.5,8036.5 h70
  text "3" at 5724.84,8036.5 h70
  text "4" at 8231.51,8036.5 h70
  text "5" at 10730.5,8036.5 h70
  text "6" at 13235.5,8036.5 h70
  text "A" at -416.5,6893.5 h70
  text "A" at 14383.5,6893.5 h70
  text "B" at -416.5,4513.5 h70
  text "B" at 14383.5,4513.5 h70
  text "C" at -416.5,2138.5 h70
  text "C" at 14383.5,2138.5 h70
  text "PROJECT TITLE:" at 11343.5,277.5 h45
  text ".PRJ_Title" at 11310,170 h40
  text "DESIGNED FOR:" at 11343.5,-23.5 h45
  text ".PRJ_Customer" at 11393.5,-163.5 h70
  text "D" at -416.5,-231.5 h70
  text "D" at 14383.5,-231.5 h70
  text "FILE NAME:" at 11343.5,-323.5 h45
  text ".PCB_File_Name_No_Path" at 11393.5,-443.5 h70
  text "Texas Instruments (TI) and/or its licensors do not warrant the accuracy or completeness of this specification" at 6374,-605.34 h45
  text "ENGINEER:" at 11343.5,-613.5 h45
  text "LAYOUT BY:" at 12848.5,-613.5 h45
  text "or any information contained therein. TI and/or its licensors do not warrant that this design will meet" at 6329.01,-718 h45
  text ".PRJ_Engineer" at 11393.5,-768.49 h70
  text ".PCB_Layout" at 12899,-768.49 h70
  text "the specifications, will be suitable for your application or fit for any particular purpose, or will operate in" at 6329.01,-830.67 h45
  text "ALTIUM DESIGNER VERSION:" at 12848.5,-923.5 h45
  text "an implementation. TI and/or its licensors do not warrant that the design is production worthy. You should" at 6329.01,-943.33 h45
  text "completely validate and test your design implementation to confirm the system functionality for your application." at 6374,-1056 h45
  text ".print_Scale" at 11393.5,-1056.83 h70
  text ".Application_BuildNumber" at 12899,-1056.83 h70
  text "1" at 739.84,-1263.5 h70
  text "2" at 3235.5,-1263.5 h70
  text "3" at 5724.84,-1263.5 h70
  text "4" at 8231.51,-1263.5 h70
  text "5" at 10730.5,-1263.5 h70
  text "6" at 13235.5,-1263.5 h70
M10 Fab Notes:
  drawing of 189 lines, arcs and shapes, not listed
  text "DESIGN INFORMATION" at 12382.02,6356.17 h60
  text "MIN. TRACK WIDTH:" at 11737.46,6224.05 h60
  text "10" at 12833.7,6224.05 h60
  text "MIL" at 12988.46,6224.05 h60
  text "MIN. CLEARANCE:" at 11737.46,6099.92 h60
  text "7.874" at 12773.7,6099.93 h60
  text "MIL" at 13075,6095 h60
  text "19.685" at 12760,5985 h60
  text "MIN. VIA PAD SIZE:" at 11737.46,5975.8 h60
  text "MIL" at 13150,5975 h60
  text "0.05mm (2MIL)" at 12432.46,5845.9 h60
  text "MINIMUM ANNULAR RING" at 11408.23,5837.67 h60
  text "EXTERNAL" at 13140.46,5837.67 h60
  text "PER" at 11608.23,5727.55 h60
  text "IPC-D-275 CLASS 2 LEVEL C" at 11828.23,5727.54 h60
  text "MIL, HOLES" at 13316.46,5627.07 h60
  text "+/-" at 12924,5618.48 h60
  text "+/-" at 13778,5618.48 h60
  text "REGISTRATION TOLERANCES:" at 11408.23,5617.42 h60
  text "METAL" at 12608,5617.42 h60
  text "5" at 13184.2,5617.42 h60
  text "3" at 14017.2,5617.42 h60
  text "MIL" at 14133.46,5617.42 h60
  text "HOLE SIZE TOLERANCE (UNLESS OTHERWISE SPECIFIED):" at 11408.23,5519.1 h60
  text "+/-" at 13778,5516.23 h60
  text "3" at 14017.2,5515.17 h60
  text "MIL" at 14133.46,5515.17 h60
  text "MATERIAL:" at 11333.46,5377.52 h60
  text "FR-4 High Tg" at 12319.9,5249 h60
  text "X" at 12175.46,5241.01 h60
  text "FR-408" at 11754.46,5236.49 h60
  text "OTHER" at 13242.46,5236.49 h60
  text "62 MIL (1.6mm) +/-10%" at 12074.56,5093.46 h60
  text "X" at 11954.46,5091.01 h60
  text "THICKNESS:" at 11408.23,5085.24 h60
  text "OTHER" at 13359.46,5085.24 h60
  text "TOLERANCE:" at 11408.23,4946.92 h60
  text "X" at 12256.46,4946.92 h60
  text "ANSI IPC-6012 TYPE 3 CLASS 2" at 12434.48,4946.92 h60
  text "OTHER +/-" at 12434.46,4802.73 h60
  text "BOW & TWIST:" at 11408.23,4657.54 h60
  text "X" at 12256.46,4657.54 h60
  text "ANSI IPC-6012 TYPE 3 CLASS 2" at 12434.48,4657.54 h60
  text "OTHER +/-" at 12434.46,4510.85 h60
  text "DRILLING:" at 11333.46,4380.23 h60
  text "NC_DRILL FILES" at 13094.46,4275.04 h60
  text "REFERENCE:" at 11408.23,4271.1 h60
  text "X" at 12065.46,4271.01 h60
  text "AS SHOWN" at 12243.46,4271.1 h60
  text "X" at 12966.46,4271.1 h60
  text "OTHER" at 13392.46,4128.85 h60
  text "PTH COPPER THICKNESS:" at 11407.91,4125.32 h60
  text "X" at 12547.14,4125.32 h60
  text "20-30 um" at 12675.14,4125.32 h60
  text "BOARD FINISH:" at 11333.46,3977.73 h60
  text "SILKSCREEN:" at 11488.68,3867.6 h60
  text "X" at 12446.46,3867.6 h60
  text "TOP" at 12563.46,3867.6 h60
  text "BOTTOM" at 13074.46,3867.6 h60
  text "SILKSCREEN COLOR:" at 11488.68,3712.41 h60
  text "X" at 12445.46,3712.41 h60
  text "WHITE" at 12563.46,3712.41 h60
  text "OTHER" at 13074.46,3712.41 h60
  text "X" at 12576.46,3568.96 h60
  text "GREEN" at 12694.46,3568.96 h60
  text "OTHER" at 13312.46,3568.96 h60
  text "SOLDER RESIST COLOR:" at 11488.68,3562.1 h60
  text "X" at 12576.46,3414.71 h60
  text "MATTE" at 12694.46,3414.71 h60
  text "SEMI-GLOSS" at 13312,3414.07 h60
  text "IMMERSION GOLD (ENIG)" at 12394.46,3241.94 h60
  text "ENEPIG" at 13732,3234.72 h60
  text "SURFACE FINISH:" at 11333.46,3233.72 h60
  text "X" at 12216.46,3233.72 h60
  text "IMM. TIN/SILVER OR EQUIV" at 11663,3096.4 h60
  text "OTHER" at 13094.46,3092.47 h60
  text "ARRAY/PANEL:" at 11333.46,2937.09 h60
  text "CUT AND TRIM PER M1 BOARD OUTLINE" at 12394.46,2928.87 h60
  text "N.C. ROUTE" at 12394.46,2792.9 h60
  text "X" at 13082.46,2792.9 h60
  text "V. SCORE" at 13260.46,2792.9 h60
  text "CERTIFICATION:" at 11333.46,2663.77 h60
  text "MATERIALS AND WORKMANSHIP FOR ALL PCBS" at 12058.46,2663.77 h60
  text "TO MEET OR EXCEED THE REQUIREMENTS OF:" at 12058.46,2569.71 h60
  text "X" at 11695.97,2441.08 h60
  text "ANSI IPC-A-600F CLASS ->" at 11823.96,2441.08 h60
  text "X" at 13471.97,2441.08 h60
  text "2" at 13581.96,2441.08 h60
  text "1" at 13266.96,2439.58 h60
  text "3" at 13935.96,2439.58 h60
  text "X" at 12507.97,2293.39 h60
  text "RoHS" at 12635.96,2293.39 h60
  text "OTHER" at 13280.36,2293.39 h60
  text "PER ORDER" at 13677.42,2293.39 h60
  text "ALL BOARDS MUST MEET OR EXCEED UL94-V0 REQUIREMENTS." at 11361,2139.57 h60
  text "PCB MUST BEAR THE UL94V-0 UL REGISTERED MATERIAL ID NUMBER" at 11361,2023.5 h60
  text "ADDITIONAL REQUIREMENTS:" at 11333.46,1854.08 h60
  text "MICROSECTION:" at 11408.23,1746.95 h60
  text "YES" at 12313.96,1746.95 h60
  text "REQUIRED" at 13175.46,1602.62 h60
  text "BARE BOARD ELEC. TEST:" at 11408.23,1599.76 h60
  text "NONE" at 12713.96,1599.76 h60
  text "X" at 13057.46,1599.76 h60
  text "PER ORDER" at 13767.46,1599.76 h60
  text "XX MIL VIAS REQUIRE NON-CONDUCTIVE FILL AND PLANARIZE" at 11576.38,1394.82 h59
  text "XX MIL VIAS REQUIRE CONDUCTIVE FILL AND PLANARIZE" at 11584.38,1290.84 h60
  text "OUTER XX MIL VIAS REQUIRE 50 OHM SINGLE-ENDED IMPEDANCE" at 11583.39,1127.46 h58
  text "LAYER 2 & 3 (INNER LAYERS) XX MIL WIDE, XX MIL SPACE / TRACES REQUIRE 100 OHM DIFFERENTIAL IMPEDANCE" at 11575.39,891.74 h60
M11 Gerber Information:
  lines w10: -292,-930.17 6308,-930.17 ; -292,-726.83 6310,-726.83 ; -292,-523.5 -292,-1133.5 3713,-1133.5 6310,-1133.5 6310,-523.5 -291.5,-523.5 -291.5,-1133.5 1284,-1133.5 ; 2173,-1133.5 2173,-523.5 ; 3440,-726.83 3440,-523.5 ; 4280,-726.83 4280,-523.5 ; 4902,-1140 4902,-937.17
  text "ALL ARTWORK VIEWED FROM TOP SIDE" at -228.5,-655.67 h60
  text "BOARD #:" at 2248,-655.67 h60
  text ".PRJ_Number" at 2793.5,-655.67 h60
  text "REV:" at 3638,-655.67 h60
  text ".PCB_Rev" at 3929.5,-655.67 h60
  text "SVN REV:" at 4476,-655.67 h60
  text ".VersionControl_RevNumber" at 4982,-655.67 h60
  text "LAYER NAME =" at -228.5,-858.49 h60
  text "TID #:" at 2248,-859 h60
  text ".TID" at 2793.5,-859 h60
  text "PLOT NAME =" at -228.5,-1064.34 h60
  text ".plot_File_Name" at 577,-1064.34 h60
  text "GENERATED    :" at 2250,-1064.34 h60
  text ".Print_Date" at 3119.5,-1064.34 h60
  text ".Print_Time" at 3848.5,-1064.34 h60
  text "TEXAS INSTRUMENTS" at 5113,-1064.34 h60
M12 Stackup:
  drawing of 295 lines, arcs and shapes, not listed
  text "Layer" at 9790.74,7845 h60
  text "Name" at 10200.65,7845 h60
  text "Material" at 11130.4,7845 h60
  text "Thickness" at 11990.16,7845 h60
  text "Constant" at 12640,7845 h60
  text "Board Layer Stack" at 13209.86,7845 h60
  text "1" at 9790.74,7725 h60
  text "Top Overlay" at 10200.65,7725 h60
  text "2" at 9790.74,7605 h60
  text "Top Solder" at 10200.65,7605 h60
  text "Solder Resist" at 11130.4,7605 h60
  text "0.40mil" at 11990.16,7605 h60
  text "3.5" at 12640,7605 h60
  text "3" at 9790.74,7485 h60
  text "Top Layer" at 10200.65,7485 h60
  text "Copper" at 11130.4,7485 h60
  text "1.40mil" at 11990.16,7485 h60
  text "4" at 9790.74,7365 h60
  text "Dielectric1" at 10200.65,7365 h60
  text "FR-4 High Tg" at 11130.4,7365 h60
  text "18.00mil" at 11990.16,7365 h60
  text "4.2" at 12640,7365 h60
  text "5" at 9790.74,7245 h60
  text "GND" at 10200.65,7245 h60
  text "Copper" at 11130.4,7245 h60
  text "1.42mil" at 11990.16,7245 h60
  text "6" at 9790.74,7125 h60
  text "Dielectric 2" at 10200.65,7125 h60
  text "FR-4 High Tg" at 11130.4,7125 h60
  text "20.00mil" at 11990.16,7125 h60
  text "4.2" at 12640,7125 h60
  text "7" at 9790.74,7005 h60
  text "PWR" at 10200.65,7005 h60
  text "Copper" at 11130.4,7005 h60
  text "1.42mil" at 11990.16,7005 h60
  text "8" at 9790.74,6885 h60
  text "Dielectric 3" at 10200.65,6885 h60
  text "FR-4 High Tg" at 11130.4,6885 h60
  text "18.00mil" at 11990.16,6885 h60
  text "4.2" at 12640,6885 h60
  text "9" at 9790.74,6765 h60
  text "Bottom Layer" at 10200.65,6765 h60
  text "Copper" at 11130.4,6765 h60
  text "1.40mil" at 11990.16,6765 h60
  text "10" at 9790.74,6645 h60
  text "Bottom Solder" at 10200.65,6645 h60
  text "Solder Resist" at 11130.4,6645 h60
  text "0.40mil" at 11990.16,6645 h60
  text "3.5" at 12640,6645 h60
  text "11" at 9790.74,6525 h60
  text "Bottom Overlay" at 10200.65,6525 h60
M16 Courtyards Bottom:
  text ".Layer_Name" at 577,-858.49 h60
Drill Drawing:
  circle w10: c5010.62,4475.83 r33.33
  lines w10: 4977.29,4609.17 4993.96,4609.17 5010.62,4592.5 5027.29,4609.17 5043.96,4609.17 5027.29,4625.83 5043.96,4642.5 5027.29,4642.5 5010.62,4659.17 4993.96,4642.5 4977.29,4642.5 4993.96,4625.83 4977.29,4609.17 ; 4977.29,4742.5 4977.29,4759.17 4993.96,4775.83 4977.29,4792.5 4977.29,4809.17 4993.96,4809.17 5010.62,4792.5 5027.29,4809.17 5043.96,4809.17 5043.96,4792.5 5027.29,4775.83 5043.96,4759.17 5043.96,4742.5 5027.29,4742.5 5010.62,4759.17 4993.96,4742.5 4977.29,4742.5 ; 4977.29,4892.5 5043.96,4892.5 5043.96,4959.17 4977.29,4959.17 4977.29,4892.5 ; 4977.29,5109.17 5043.96,5109.17 5010.62,5042.5 4977.29,5109.17 ; 4977.29,5192.5 5010.62,5209.17 5043.96,5192.5 5027.29,5225.83 5043.96,5259.17 5010.62,5242.5 4977.29,5259.17 4993.96,5225.83 4977.29,5192.5 ; 4977.29,5359.17 4993.96,5359.17 4993.96,5342.5 5027.29,5342.5 5027.29,5359.17 5043.96,5359.17 5043.96,5392.5 5027.29,5392.5 5027.29,5409.17 4993.96,5409.17 4993.96,5392.5 4977.29,5392.5 4977.29,5359.17 ; 4977.29,5525.83 5010.62,5492.5 5043.96,5525.83 5010.62,5559.17 4977.29,5525.83
  lines w15: 4917.5,4397.5 8442.58,4397.5 ; 4917.5,5597.5 8442.58,5597.5 ; 5468.38,4247.5 5468.38,5747.5 ; 6008.24,4247.5 6008.24,5747.5 ; 7157.9,4247.5 7157.9,5747.5 ; 7663.78,4247.5 7663.78,5747.5 ; 4917.5,4247.5 8442.58,4247.5 8442.58,5747.5 4917.5,5747.5 4917.5,4247.5
  text "Symbol" at 5007.5,5642.5 h72
  text "Count" at 5513.38,5642.5 h72
  text "Hole Size" at 6053.24,5642.5 h72
  text "Plated" at 7202.9,5642.5 h72
  text "Hole Type" at 7708.78,5642.5 h72
  text "2" at 5513.38,5492.5 h60
  text "7.87mil (0.200mm)" at 6053.24,5492.5 h60
  text "PTH" at 7202.9,5492.5 h60
  text "Round" at 7708.78,5492.5 h60
  text "48" at 5513.38,5342.5 h60
  text "16.00mil (0.406mm)" at 6053.24,5342.5 h60
  text "PTH" at 7202.9,5342.5 h60
  text "Round" at 7708.78,5342.5 h60
  text "6" at 5513.38,5192.5 h60
  text "39.37mil (1.000mm)" at 6053.24,5192.5 h60
  text "PTH" at 7202.9,5192.5 h60
  text "Round" at 7708.78,5192.5 h60
  text "6" at 5513.38,5042.5 h60
  text "40.00mil (1.016mm)" at 6053.24,5042.5 h60
  text "PTH" at 7202.9,5042.5 h60
  text "Round" at 7708.78,5042.5 h60
  text "3" at 5513.38,4892.5 h60
  text "40.16mil (1.020mm)" at 6053.24,4892.5 h60
  text "PTH" at 7202.9,4892.5 h60
  text "Round" at 7708.78,4892.5 h60
  text "2" at 5513.38,4742.5 h60
  text "43.31mil (1.100mm)" at 6053.24,4742.5 h60
  text "NPTH" at 7202.9,4742.5 h60
  text "Round" at 7708.78,4742.5 h60
  text "2" at 5513.38,4592.5 h60
  text "43.31mil (1.100mm)" at 6053.24,4592.5 h60
  text "PTH" at 7202.9,4592.5 h60
  text "Round" at 7708.78,4592.5 h60
  text "4" at 5513.38,4442.5 h60
  text "125.98mil (3.200mm)" at 6053.24,4442.5 h60
  text "PTH" at 7202.9,4442.5 h60
  text "Round" at 7708.78,4442.5 h60
  text "73 Total" at 5513.38,4292.5 h60
  text "Drill tolerances:" at 5874,3827 h75
  text "For 16 mil drill via +0/-16 mil" at 5881,3647 h75
  text "For 7.87 mil drill via +0/-7.87 mil" at 5870,3495 h75
  text "For  PTH +/-3 mil" at 5856,3362 h75
  text "For  NPTH +/-2 mil" at 5856,3232 h75
  text "Vias are non tented" at 5925,2865 h75
  text "It is not a impedence controlled board." at 5925,2740 h75
  text ".Layer_Name" at 577,-858.49 h60
M17 Embedded Cavity:
  text ".Layer_Name" at 577,-858.49 h60
M18 Embedded Assembly:
  text ".Layer_Name" at 577,-858.49 h60
M19 Embedded Keepout:
  text ".Layer_Name" at 577,-858.49 h60

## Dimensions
0,0 to 2362.2,0 on M2 Board Dimensions
0,0 to 0,1653.54 on M2 Board Dimensions
0,-400 to 1000,-400 on M2 Board Dimensions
